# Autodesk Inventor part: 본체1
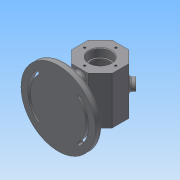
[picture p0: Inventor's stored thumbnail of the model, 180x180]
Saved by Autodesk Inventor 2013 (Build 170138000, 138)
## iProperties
Created: 2017-06
Part Number: 본체1
Material: 일반
Document SubType Name: Modeling
Designer: Administrator
Density: 1 g/cm^3
Author: Administrator
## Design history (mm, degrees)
sketch "스케치1" dims "d0" = 60
  geometry: L1 (12.426, 30)-(30, 12.426); L2 (30, 12.426)-(30, -12.426); L3 (30, -12.426)-(12.426, -30); L4 (12.426, -30)-(-12.426, -30); L5 (-12.426, -30)-(-30, -12.426); L6 (-30, -12.426)-(-30, 12.426); L7 (-30, 12.426)-(-12.426, 30); L8 (-12.426, 30)-(12.426, 30); L9 (12.426, 30)-(-12.426, -30); L10 (-30, 12.426)-(30, -12.426); 6 further points
  constraints: 20 end point, 3 midpoint, 2 coincident, 1 horizontal alignment, 1 perpendicular, 1 vertical alignment, 19 other
  dimensions: "d1" = 60 distance between parallel lines of L4 L8 (derived); "d2" = 64.94353 distance of L4.end L1.start (derived)
extrude "돌출1" new body sketch "스케치1" stored distance "d3" = 70; taper "d4" = 0 deg
sketch "스케치2"
  geometry: L1 (0, 35)-(0, -35); L2 (30, -35)-(-30, -35) reference; L3 (-30, -35)-(-30, 35) reference; L4 (-30, 35)-(30, 35) reference; L5 (30, 35)-(30, -35) reference; L6 (0, 35)-(16, 35); L7 (16, 35)-(16, 23); L8 (16, 23)-(14, 23); L9 (14, 23)-(14, 20); L10 (14, 20)-(25, 20); L11 (14, -20)-(14, -23); L12 (14, -23)-(16, -23); L13 (16, -23)-(16, -35); L14 (16, -35)-(0, -35); L15 (14, -20)-(25, -20); L16 (25, 20)-(25, -20); 2 further points
  constraints: 24 end point, 5 parallel, 4 collinear, 3 perpendicular, 2 point on line, 1 coincident, 1 midpoint, 1 vertical
  dimensions: "d7" = 32 diameter of L7 L1; "d9" = 32 diameter of L13 L1 (derived); "d11" = 50 diameter of L16 L1; "d12" = 28 diameter of L9 L1; "d13" = 28 diameter of L11 L1; "d14" = 12 distance of L6.end L7.end; "d15" = 40 distance of L10.end L15.end
revolve "회전1" sketch "스케치2" stored, may be unused: angle "d16" = 90 deg
sketch "스케치3" dims "d17" = 46
  geometry: C1 r 16 at (0, 0) reference; 2 further points
  constraints: 2 vertical alignment, 1 coincident, 2 other
hole "구멍1" sketch "스케치3" at (0, 23) diameter "d18" = 3.242; stored, may be unused: countersink angle "d22" = 90 deg, drill point angle "d24" = 118 deg; dims "d19" = 8, "d20" = 4, "d21" = 2, "d23" = 10
node "작업 평면1"
sketch "스케치4"
  geometry: C1 r 55 at (0, 0); 1 further point
  constraints: 1 centre point, 1 coincident
  dimensions: "d29" = 110 diameter of C1
extrude "돌출2" join sketch "스케치4" distance "d30" = 10; taper "d31" = 0 deg
sketch "스케치6"
  geometry: L1 (0, 0)-(48, 0); L2 (0, 0)-(48, 0); L3 (0, 0)-(50, 0); L4 (0, 0)-(50, 0); L5 (0, 0)-(30.406, 30.406); L6 (0, 0)-(30.406, -30.406); C1 r 55 at (0, 0) reference; A1 r 48 centre (0, 0) between (33.941, -33.941) and (33.941, 33.941); A2 r 38 centre (0, 0) between (26.87, -26.87) and (26.87, 26.87); A3 r 43 centre (0, 0) between (30.406, -30.406) and (30.406, 30.406); A4 r 5 centre (30.406, 30.406) between (33.941, 33.941) and (26.87, 26.87); A5 r 5 centre (30.406, -30.406) between (26.87, -26.87) and (33.941, -33.941); A6 r 2 centre (30.406, 30.406) between (31.82, 31.82) and (28.991, 28.991); A7 r 45 centre (0, 0) between (31.82, -31.82) and (31.82, 31.82); A8 r 2 centre (30.406, -30.406) between (28.991, -28.991) and (31.82, -31.82); A9 r 41 centre (0, 0) between (28.991, -28.991) and (28.991, 28.991)
  constraints: 18 point on circle, 12 end point, 9 centre point, 6 coincident, 4 horizontal, 1 perpendicular, 3 other
  dimensions: "d42" = 96 diameter of A1; "d43" = 76 diameter of A2; "d44" = 86 diameter of A3; "d59" = 45 deg angle of L1 L5; "d60" = 10 diameter of A4; "d61" = 10 diameter of A5; "d62" = 3 radial gap between concentric circles of A1 A7; "d63" = 5 radius of A4 (derived); "d64" = 2 radius of A6 (derived)
extrude "돌출3" cut sketch "스케치6" distance "d65" = 3; taper "d66" = 0 deg
extrude "돌출4" cut sketch "스케치6" stored distance "d67" = 3; taper "d68" = 0 deg
sketch "스케치7"
  geometry: L1 (5, 24)-(-5, 24); L2 (-5, 24)-(-5, -24); L3 (-5, -24)-(5, -24); L4 (5, -24)-(5, 24); L5 (5, 24)-(-5, -24); L6 (-5, 24)-(5, -24); L7 (0, 24)-(0, -24); A1 r 38 centre (0, 0) between (26.87, -26.87) and (26.87, 26.87) reference; A2 r 5 centre (0, 24) between (5, 24) and (-5, 24); A3 r 5 centre (0, -24) between (-5, -24) and (5, -24)
  constraints: 14 end point, 4 midpoint, 4 point on circle, 2 centre point, 2 parallel, 2 perpendicular, 1 horizontal
  dimensions: "d72" = 10 distance of L3.end L2.end; "d73" = 48 distance of L1.end L2.end
extrude "돌출5" join sketch "스케치7" stored distance "d74" = 3; taper "d75" = 0 deg
sketch "스케치8"
  geometry: L1 (-48, -52)-(-48, -55) reference; L2 (-48, -55)-(-45, -55) reference; L3 (-45, -55)-(-45, -62) reference; L4 (-45, -62)-(-55, -62) reference; L5 (-55, -62)-(-55, -52) reference; L6 (-55, -52)-(-48, -52) reference; L7 (38, -52)-(38, -55) reference; L8 (38, -55)-(41, -55) reference; L9 (41, -55)-(41, -62) reference; L10 (41, -62)-(-41, -62) reference; L11 (-41, -62)-(-41, -55) reference; L12 (-41, -55)-(-38, -55) reference; L13 (-38, -55)-(-38, -52) reference; L14 (-38, -52)-(-5, -52) reference; L15 (-5, -52)-(-5, -30) reference; L16 (-5, -30)-(-12.426, -30) reference; L17 (-12.426, -30)-(-30, -12.426) reference; L18 (-30, -12.426)-(-30, 12.426) reference; L19 (-30, 12.426)-(-12.426, 30) reference; L20 (-12.426, 30)-(12.426, 30) reference; L21 (12.426, 30)-(30, 12.426) reference; L22 (30, 12.426)-(30, -12.426) reference; L23 (30, -12.426)-(12.426, -30) reference; L24 (12.426, -30)-(5, -30) reference; L25 (5, -30)-(5, -52) reference; L26 (5, -52)-(38, -52) reference; L27 (48, -55)-(48, -52) reference; L28 (48, -52)-(55, -52) reference; L29 (55, -52)-(55, -62) reference; L30 (55, -62)-(45, -62) reference; L31 (45, -62)-(45, -55) reference; L32 (45, -55)-(48, -55) reference; L33 (0, 0)-(21.213, 21.213); L34 (0, 0)-(30, 0); C1 r 25 at (0, 0) reference; 1 further point
  constraints: 4 end point, 1 equal length, 1 horizontal, 1 midpoint
  dimensions: "d76" = 45 deg angle of L34 L33
  node "절단 모서리 투영2"
node "작업 평면4"
sketch "스케치9"
  geometry: C1 r 8 at (0, 0); 1 further point
  constraints: 1 centre point, 1 coincident
  dimensions: "d83" = 16 diameter of C1
extrude "돌출6" join sketch "스케치9" distance "d84" = 7; taper "d85" = 0 deg
hole "구멍2" diameter "d88" = 8; stored, may be unused: countersink angle "d92" = 90 deg, drill point angle "d94" = 0 deg; dims "d86" = 10, "d87" = 10, "d89" = 8, "d90" = 4, "d91" = 2, "d93" = 10
chamfer "모따기1" distance "d95" = 1; stored, may be unused: second distance "d96" = 2, angle "d97" = 45 deg
sketch "스케치10"
  geometry: 1 further point
fillet "모깎기1" dims "d98" = 0.3
fillet "모깎기2" dims "d99" = 3
sketch "스케치11"
  geometry: L1 (24.853, 0)-(0, 0) reference; 2 further points
  constraints: 1 coincident, 1 other
  dimensions: "d101" = 35 distance from line of point (12.426, 35) L1 (derived)
feature "엠보싱1" sketch "스케치11" dims "d102" = 0.5, "d103" = 0
fillet "모깎기3" dims "d104" = 1
fillet "모깎기4" dims "d105" = 3
fillet "모깎기5" dims "d106" = 5
node "솔리드1"
pattern_circular "원형 패턴1" dims angle "d26" = 360 deg
mirror "대칭1"
pattern_circular "원형 패턴2" dims angle "d70" = 360 deg
node "절단 모서리 투영1"
other parameters: "d28" = -62, "d77" = 0, "d78" = 0, "d79" = 0, "d80" = 0, "d81" = 0, "d82" = 0
